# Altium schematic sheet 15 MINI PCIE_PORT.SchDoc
size 420 x 297 mm
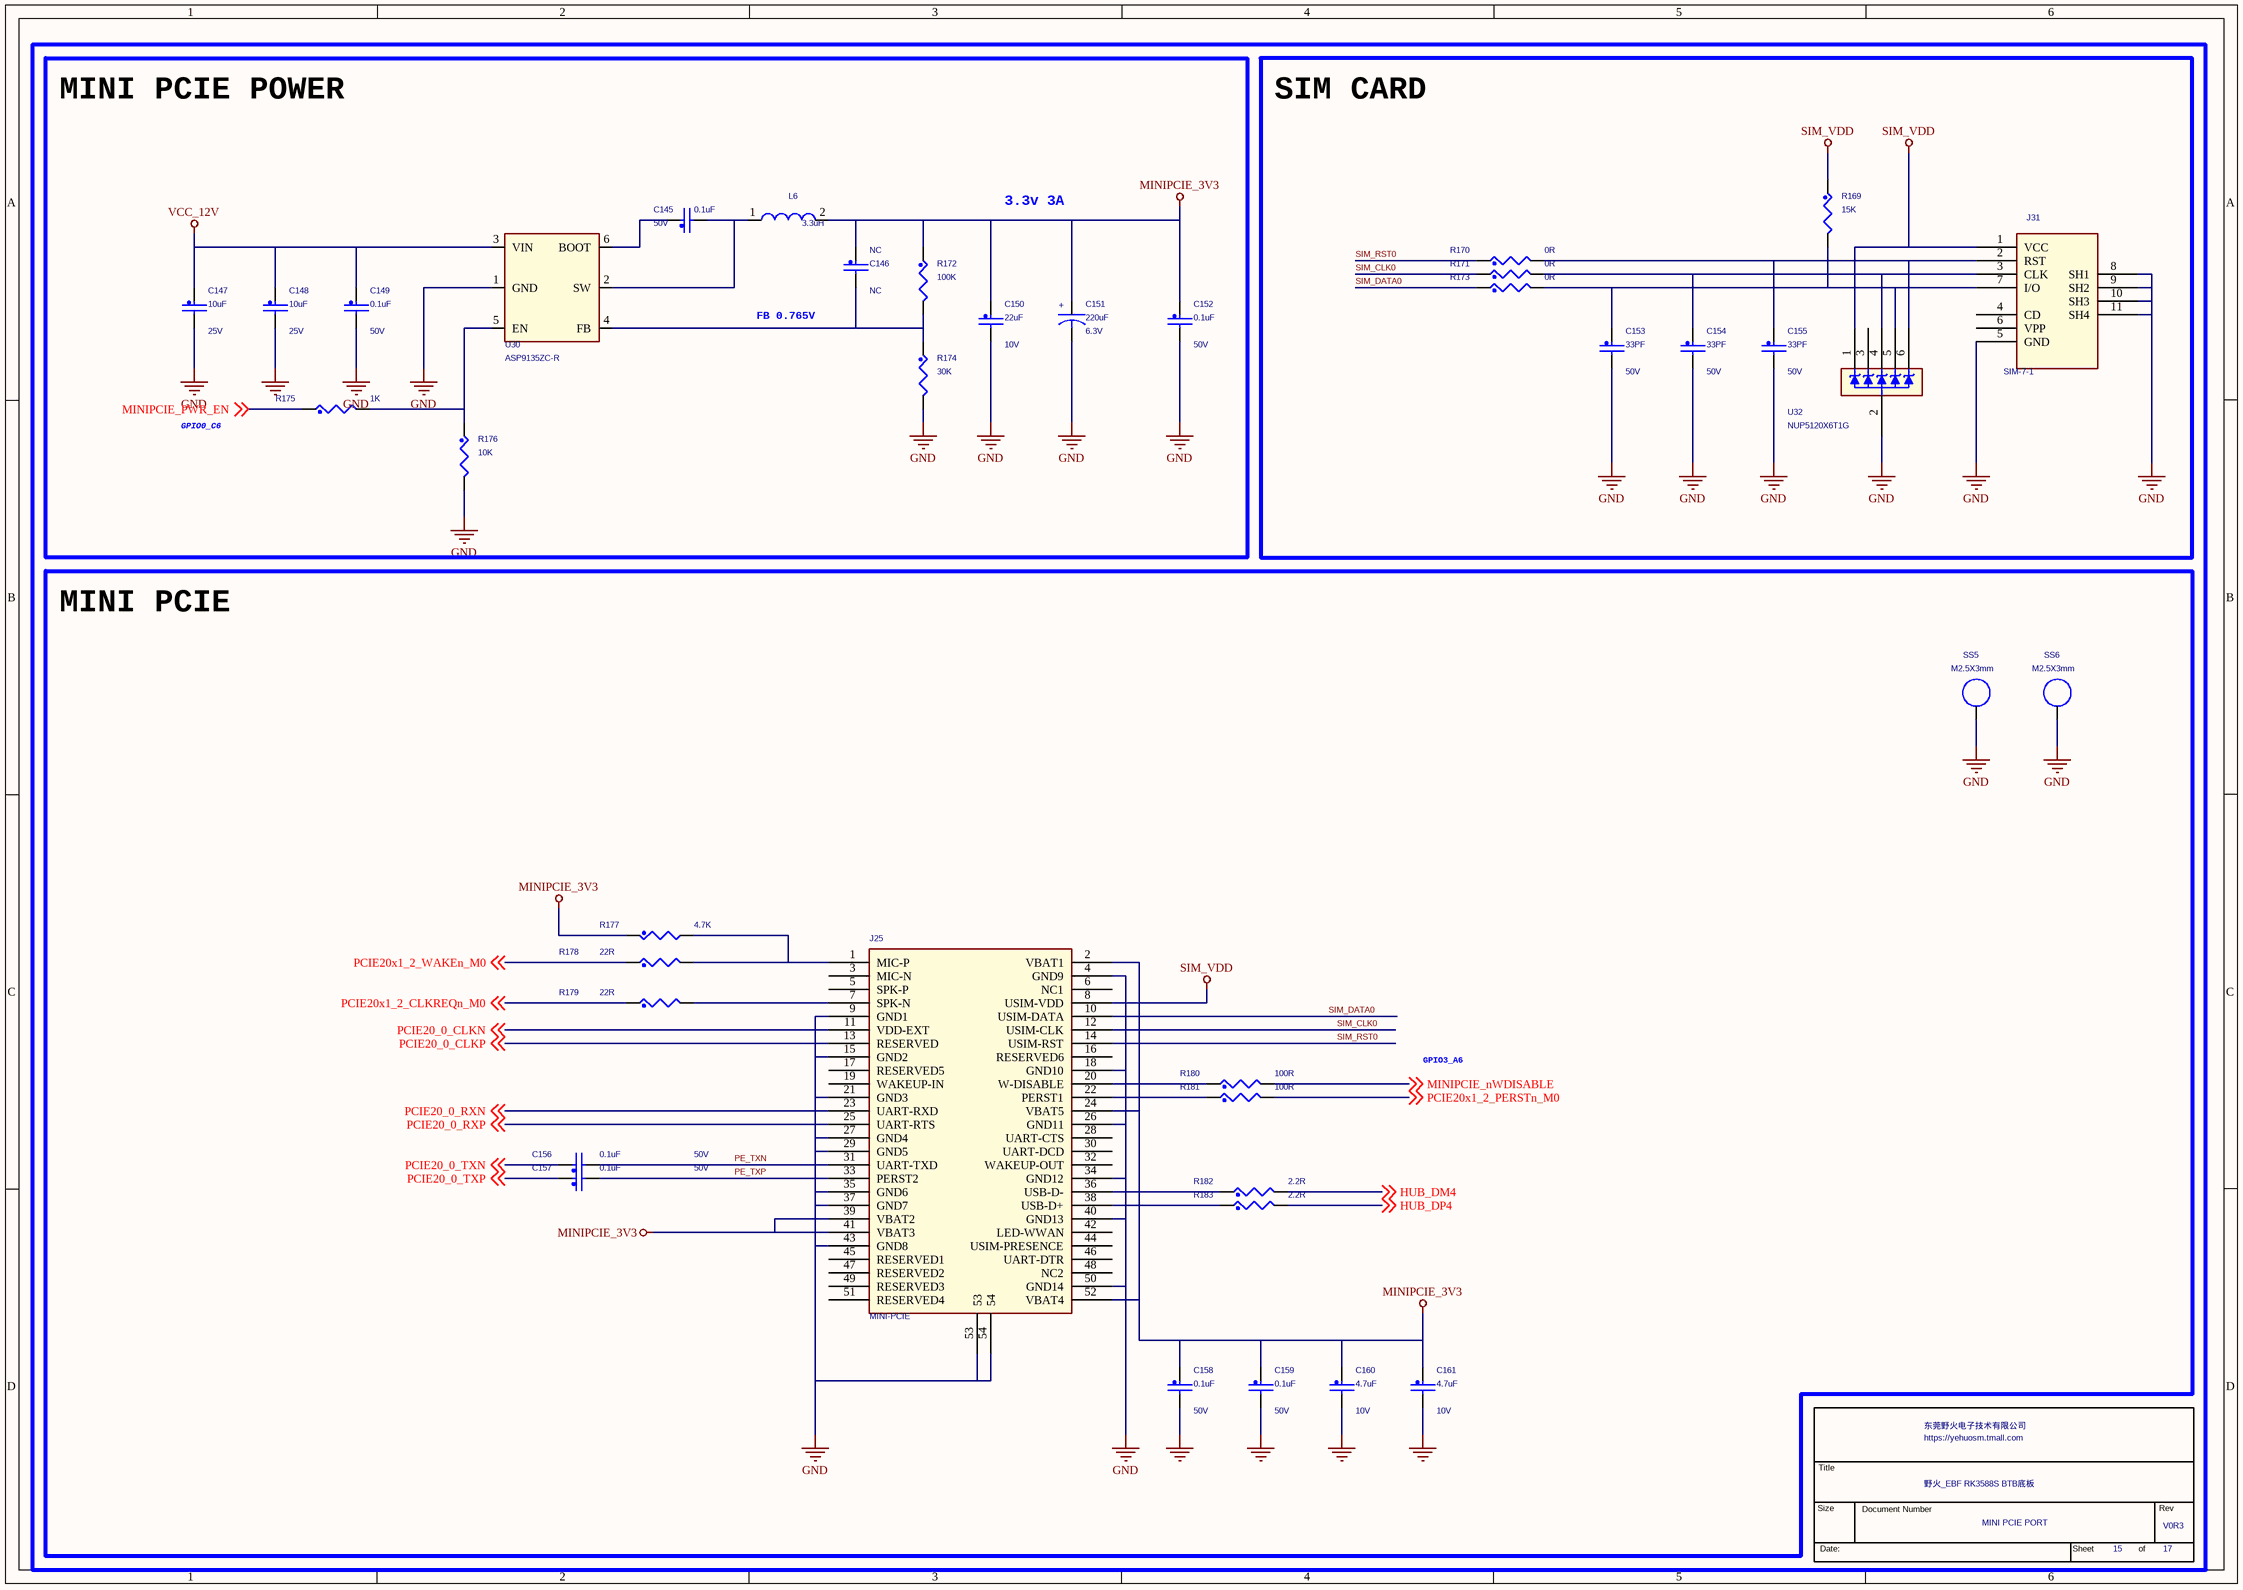
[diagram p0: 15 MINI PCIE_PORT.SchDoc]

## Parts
*  Page Count: 17  Page Number: 15  OrgName: 东莞野火电子技术有限公司  Title: 野火_EBF RK3588S BTB底板  RevCode: V0R3  Doc: MINI PCIE PORT  (hidden comment: TitleBlock_YHSCH)  (graphical)
C145  0.1uF  Voltage: 50V  [C0402]
C146  NC  [C0402]
C147  10uF  Voltage: 25V  [C0603]
C148  10uF  Voltage: 25V  [C0603]
C149  0.1uF  Voltage: 50V  [C0402]
C150  22uF  Voltage: 10V  [C0603]
C151  220uF  Voltage: 6.3V  [T2012]
C152  0.1uF  Voltage: 50V  [C0402]
C153  33PF  Voltage: 50V  [C0402]
C154  33PF  Voltage: 50V  [C0402]
C155  33PF  Voltage: 50V  [C0402]
C156  0.1uF  Voltage: 50V  [C0402]
C157  0.1uF  Voltage: 50V  [C0402]
C158  0.1uF  Voltage: 50V  [C0402]
C159  0.1uF  Voltage: 50V  [C0402]
C160  4.7uF  Voltage: 10V  [C0402]
C161  4.7uF  Voltage: 10V  [C0402]
J25  MINI-PCIE  [pcie_52p]
J31  SIM-7-1  [nano_sim]
L6  3.3uH  [l4520]
R169  15K  [R0402]
R170  0R  [R0402]
R171  0R  [R0402]
R172  100K  [R0402]
R173  0R  [R0402]
R174  30K  [R0402]
R175  1K  [R0402]
R176  10K  [R0402]
R177  4.7K  [R0402]
R178  22R  [R0402]
R179  22R  [R0402]
R180  100R  [R0402]
R181  100R  [R0402]
R182  2.2R  [R0402]
R183  2.2R  [R0402]
SS5  M2.5X3mm  [SMTSO-M2r5]
SS6  M2.5X3mm  [SMTSO-M2r5]
U30  ASP9135ZC-R  [SOT23_6]
U32  NUP5120X6T1G  [SOT563]

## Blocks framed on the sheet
MINI PCIE POWER: C145-C152 L6 R172 R174-R176 U30
SIM CARD: C153-C155 J31 R169-R171 R173 U32
MINI PCIE: C156-C161 J25 R177-R183 SS5 SS6

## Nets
GND: C147.2 C148.2 C149.2 C150.2 C151.2 C152.2 C153.2 C154.2 C155.2 C158.2 C159.2 C160.2 C161.2 J25.4(GND9) J25.9(GND1) J25.15(GND2) J25.18(GND10) J25.21(GND3) J25.26(GND11) J25.27(GND4) J25.29(GND5) J25.34(GND12) J25.35(GND6) J25.37(GND7) J25.40(GND13) J25.43(GND8) J25.50(GND14) J25.53 J25.54 J31.5(GND) J31.8(SH1) J31.9(SH2) J31.10(SH3) J31.11(SH4) R174.2 R176.2 SS5.1(NC_1) SS6.1(NC_1) U30.1(GND) U32.2
MINIPCIE_3V3: C146.1 C150.1 C151.1 C152.1 C158.1 C159.1 C160.1 C161.1 J25.2(VBAT1) J25.24(VBAT5) J25.39(VBAT2) J25.41(VBAT3) J25.52(VBAT4) L6.2 R172.1 R177.1
SIM_VDD: J25.8(USIM-VDD) J31.1(VCC) R169.1 U32.1
VCC_12V: C147.1 C148.1 C149.1 U30.3(VIN)
HUB_DM4: R182.2 ; off-sheet HUB_DM4
HUB_DP4: R183.2 ; off-sheet HUB_DP4
MINIPCIE_nWDISABLE: R180.2 ; off-sheet MINIPCIE_nWDISABLE
MINIPCIE_PWR_EN: R175.1 ; off-sheet MINIPCIE_PWR_EN
PCIE20_0_CLKN: J25.11(VDD-EXT) ; off-sheet PCIE20_0_CLKN
PCIE20_0_CLKP: J25.13(RESERVED) ; off-sheet PCIE20_0_CLKP
PCIE20_0_RXN: J25.23(UART-RXD) ; off-sheet PCIE20_0_RXN
PCIE20_0_RXP: J25.25(UART-RTS) ; off-sheet PCIE20_0_RXP
PCIE20_0_TXN: C156.1 ; off-sheet PCIE20_0_TXN
PCIE20_0_TXP: C157.1 ; off-sheet PCIE20_0_TXP
PCIE20x1_2_CLKREQn_M0: R179.1 ; off-sheet PCIE20x1_2_CLKREQn_M0
PCIE20x1_2_PERSTn_M0: R181.2 ; off-sheet PCIE20x1_2_PERSTn_M0
PCIE20x1_2_WAKEn_M0: R178.1 ; off-sheet PCIE20x1_2_WAKEn_M0
PE_TXN: C156.2 J25.31(UART-TXD)
PE_TXP: C157.2 J25.33(PERST2)
SIM_CLK0: J25.12(USIM-CLK) R171.1
SIM_DATA0: J25.10(USIM-DATA) R173.1
SIM_RST0: J25.14(USIM-RST) R170.1
NetC145_1: C145.1 U30.6(BOOT)
NetC145_2: C145.2 L6.1 U30.2(SW)
NetC146_2: C146.2 R172.2 R174.1 U30.4(FB)
NetC153_1: C153.1 J31.7(I/O) R169.2 R173.2 U32.5
NetC154_1: C154.1 J31.3(CLK) R171.2 U32.4
NetC155_1: C155.1 J31.2(RST) R170.2 U32.6
NetJ25_1: J25.1(MIC-P) R177.2 R178.2
NetJ25_7: J25.7(SPK-N) R179.2
NetJ25_20: J25.20(W-DISABLE) R180.1
NetJ25_22: J25.22(PERST1) R181.1
NetJ25_36: J25.36(USB-D-) R182.1
NetJ25_38: J25.38(USB-D+) R183.1
NetR175_2: R175.2 R176.1 U30.5(EN)

Not connected (* = marked no-connect by the designer): J25 3(MIC-N) 5(SPK-P) 6(NC1) 16(RESERVED6) 17(RESERVED5) 19(WAKEUP-IN) 28(UART-CTS) 30(UART-DCD) 32(WAKEUP-OUT) 42(LED-WWAN) 44(USIM-PRESENCE) 45(RESERVED1) 46(UART-DTR) 47(RESERVED2) 48(NC2) 49(RESERVED3) 51(RESERVED4); J31 4(CD) 6(VPP); U32 3

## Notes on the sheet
- 3.3v 3A
- FB 0.765V
- GPIO0_C6
- GPIO3_A6

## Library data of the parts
* = TitleBlock_YHSCH: Cage Code: 1
C145 C152 C158 C159 = CAP_NP: CLASS: DISCRETE; 规格: 贴片电容0.1uF 10% 50V X5R 0402; 规格编号: 0402X104K500NT; 条码: EBF29060118; 品牌: 风华; 类别: 贴片电容0402; 规格书: 风华电容.pdf; 价格: 0.029826; 生命周期: 量产
C146 = CAP_NP: CLASS: DISCRETE; 类别: 贴片电容0402; 条码: EBF29060149; 规格: 贴片电容NC 预留
C147 C148 = CAP_NP: CLASS: DISCRETE; 规格: 贴片电容10uF 20% 25V X5R 0603; 规格编号: CL10A106MA8NRNC; 条码: EBF29060171; 品牌: 三星; 类别: 贴片电容0603; 规格书: 三星电容.pdf; 生命周期: 量产; 价格: 0.109811
C149 = CAP_NP: CLASS: DISCRETE; 生命周期: 量产; 价格: 0.029826; 规格书: 风华电容.pdf; 类别: 贴片电容0402; 品牌: 风华; 条码: EBF29060118; 规格编号: 0402X104K500NT; 规格: 贴片电容0.1uF 10% 50V X5R 0402
C150 = CAP_NP: CLASS: DISCRETE; 生命周期: 量产; 价格: 0.078818; 规格书: 三星电容.pdf; 类别: 贴片电容0603; 品牌: 三星; 条码: EBF29060163; 规格编号: CL10A226MP8NUNE; 规格: 贴片电容22uF 20% 10V X5R 0603
C151 = CAP: 规格: 贴片电容220uF 20% 6.3V 坦电容 CASE-B_3528; 规格编号: TLJB227M006R0500; 条码: EBF29060264; 品牌: AVX; 类别: 贴片坦电容; 规格书: AVX_贴片坦电容.pdf; 价格: 1.28; 生命周期: 量产
C153 C154 = CAP_NP: CLASS: DISCRETE; 规格: 贴片电容33pF 5% 50V 0402; 规格编号: 0402CG330J500NT; 条码: EBF29060298; 品牌: 风华; 类别: 贴片电容0402; 规格书: 风华电容.pdf; 生命周期: 量产
C155 = CAP_NP: CLASS: DISCRETE; 生命周期: 量产; 规格书: 风华电容.pdf; 类别: 贴片电容0402; 品牌: 风华; 条码: EBF29060298; 规格编号: 0402CG330J500NT; 规格: 贴片电容33pF 5% 50V 0402
C156 C157 = CAP_NP: CLASS: DISCRETE; 价格: 0.029826; 规格: 贴片电容0.1uF 10% 50V X5R 0402; 规格编号: 0402X104K500NT; 条码: EBF29060118; 品牌: 风华; 类别: 贴片电容0402; 规格书: 风华电容.pdf; 生命周期: 量产
C160 = CAP_NP: CLASS: DISCRETE; 生命周期: 量产; 价格: 0.059058; 规格书: 国巨-贴片电容.pdf; 类别: 贴片电容0402; 品牌: 国巨; 条码: EBF29060248; 规格编号: CC0402KRX5R6BB475; 规格: 贴片电容4.7uF 10% 10V X5R 0402
C161 = CAP_NP: CLASS: DISCRETE; 规格: 贴片电容4.7uF 10% 10V X5R 0402; 规格编号: CC0402KRX5R6BB475; 条码: EBF29060248; 品牌: 国巨; 类别: 贴片电容0402; 规格书: 国巨-贴片电容.pdf; 价格: 0.059058; 生命周期: 量产
J25 = MINI-PCIE: 可替代料: EBF29040055; 生命周期: 量产; 价格: 1.935; 规格书: XUNPU(讯普)_52PMINIPCIE插座.pdf; 类别: 金手指连接器; 品牌: 讯普; 规格编号: PCIE-52P56H; 规格: MINI PCIE插座 引脚数：52P
J31 = SIM-7-1: 规格: nano sim卡座; 规格编号: HYC63-SIM07-137; 条码: EBF29040054; 品牌: 华宇创; 类别: SIM卡座连接器; 规格书: 华宇创_NANOSIMPUSH1.37H带CDPIN带柱.pdf; 价格: 1.48; 生命周期: 量产
L6 = IND: CLASS: DISCRETE; 生命周期: 量产; 规格书: 台庆-功率电感.pdf; 类别: 贴片电感0402; 品牌: 台庆; 条码: EBF29050040; 规格: 贴片电感3.3uH ±20% 3A 直流电阻69mΩ; 规格编号: TMPC0402HP-3R3MG-Z02; 价格: 1.5992
R169 = RES: CLASS: DISCRETE; 生命周期: 量产; 规格书: 合科泰-RI系列电阻.pdf; 类别: 贴片电阻0402; 品牌: 合科泰; 条码: EBF29070222; 规格编号: RI0402L1502FT; 规格: 贴片电阻15K 1% 1/16W 0402
R170 R171 R173 = RES: CLASS: DISCRETE; 规格: 贴片电阻0R 1% 1/16W 0402; 规格编号: RI0402L000FT; 条码: EBF29070049; 品牌: 合科泰; 类别: 贴片电阻0402; 规格书: 合科泰-RI系列电阻.pdf; 生命周期: 量产
R172 = RES: CLASS: DISCRETE; 生命周期: 量产; 规格书: 合科泰-RI系列电阻.pdf; 类别: 贴片电阻0402; 品牌: 合科泰; 条码: EBF29070054; 规格编号: RI0402L1003FT; 规格: 贴片电阻100K 1% 1/16W 0402
R174 = RES: CLASS: DISCRETE; 生命周期: 量产; 规格书: 合科泰-RI系列电阻.pdf; 类别: 贴片电阻0402; 品牌: 合科泰; 条码: EBF29070048; 规格编号: RI0402L3002FT; 规格: 贴片电阻30K 1% 1/16W 0402
R175 = RES: CLASS: DISCRETE; 类别: 贴片电阻0402; 条码: EBF29070050; 规格: 贴片电阻1K 1% 1/16W 0402; 规格编号: RI0402L1001FT; 品牌: 合科泰; 规格书: 合科泰-RI系列电阻.pdf; 生命周期: 量产
R176 = RES: CLASS: DISCRETE; 规格: 贴片电阻10K 1% 1/16W 0402; 规格编号: 0402WGF1002TCE; 条码: EBF29070046; 品牌: 厚声; 类别: 贴片电阻0402; 规格书: 厚声-无铅厚膜电阻.pdf; 价格: 0.002773; 生命周期: 量产
R177 = RES: CLASS: DISCRETE; 生命周期: 量产; 规格书: 合科泰-RI系列电阻.pdf; 类别: 贴片电阻0402; 品牌: 合科泰; 条码: EBF29070047; 规格编号: RI0402L4701FT; 规格: 贴片电阻4.7K 1% 1/16W 0402
R178 R179 = RES: CLASS: DISCRETE; 生命周期: 量产; 规格书: 合科泰-RI系列电阻.pdf; 类别: 贴片电阻0402; 品牌: 合科泰; 条码: EBF29070181; 规格编号: RI0402L22R0FT; 规格: 贴片电阻22R 1% 1/16W 0402
R180 = RES: CLASS: DISCRETE; 规格: 贴片电阻100R 1% 1/16W 0402; 规格编号: RI0402L1000FT; 条码: EBF29070053; 品牌: 合科泰; 类别: 贴片电阻0402; 规格书: 合科泰-RI系列电阻.pdf; 生命周期: 量产
R181 = RES: CLASS: DISCRETE; 生命周期: 量产; 规格书: 合科泰-RI系列电阻.pdf; 类别: 贴片电阻0402; 品牌: 合科泰; 条码: EBF29070053; 规格编号: RI0402L1000FT; 规格: 贴片电阻100R 1% 1/16W 0402
R182 = RES: CLASS: DISCRETE; 生命周期: 量产; 价格: 0.003072; 规格书: 厚声-无铅厚膜电阻.pdf; 类别: 贴片电阻0402; 品牌: 厚声; 条码: EBF29070280; 规格编号: 0402WGF220KTCE; 规格: 贴片电阻2.2R 1% 1/16W 0402
R183 = RES: CLASS: DISCRETE; 规格: 贴片电阻2.2R 1% 1/16W 0402; 规格编号: 0402WGF220KTCE; 条码: EBF29070280; 品牌: 厚声; 类别: 贴片电阻0402; 规格书: 厚声-无铅厚膜电阻.pdf; 价格: 0.003072; 生命周期: 量产
SS5 = SPACER: CLASS: IC; 规格书: 雄和远景_SMTSO2530CTJ.pdf; 规格: SMT贴片螺母M2.5 台阶高度1.4MM 台阶外径：4.09MM 螺柱长度：3MM; 规格编号: SMTSO2530CTJ; 条码: EBFCIS221028102827; 品牌: 雄和远景; 类别: 贴片螺母; 生命周期: 量产
SS6 = SPACER: CLASS: IC; 规格: SMT贴片螺母M2.5 台阶高度1.4MM 台阶外径：4.09MM 螺柱长度：3MM; 规格编号: SMTSO2530CTJ; 条码: EBFCIS221028102827; 品牌: 雄和远景; 类别: 贴片螺母; 生命周期: 量产; 规格书: 雄和远景_SMTSO2530CTJ.pdf
U30 = TP6327GS6: 备注: RK3566金手指与BTB底板替换物料; 生命周期: 量产; 规格书: 安森德_ASP9135ZC-R.pdf; 类别: 电源管理-DCDC; 品牌: 安森德; 条码: EBFCIS240710113940; 规格: DC-DC电源芯片 可输出电流 3A 开关工作频率 600kHz 输出类型 ADJ 输入电压范围：4V-18V
U32 = NUP5120-D: 规格: 防静电保护ESD二极管 击穿电压6.2V 反向关断电压5V 封装SOT-523; 条码: EBF29140034; 品牌: 安森美; 类别: 贴片ESD; 规格书: 安森美_NUP5120X6T1G.pdf; 价格: 0.39; 生命周期: 量产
